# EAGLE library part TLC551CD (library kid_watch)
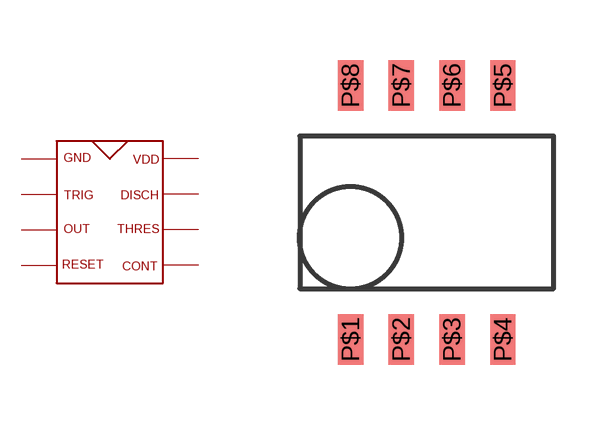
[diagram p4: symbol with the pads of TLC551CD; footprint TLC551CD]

Designator prefix -

## TLC551CD  [TLC551CD]
P$1  P$1
P$2  P$2
P$3  P$3
P$4  P$4
P$5  P$5
P$6  P$6
P$7  P$7
P$8  P$8

## Footprint TLC551CD (pad centres in mm)
smd 0.635 x 1.27: P$1 0,0; P$2 1.27,0; P$3 2.54,0; P$4 3.81,0; P$5 3.81,6.35; P$6 2.54,6.35; P$7 1.27,6.35; P$8 0,6.35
